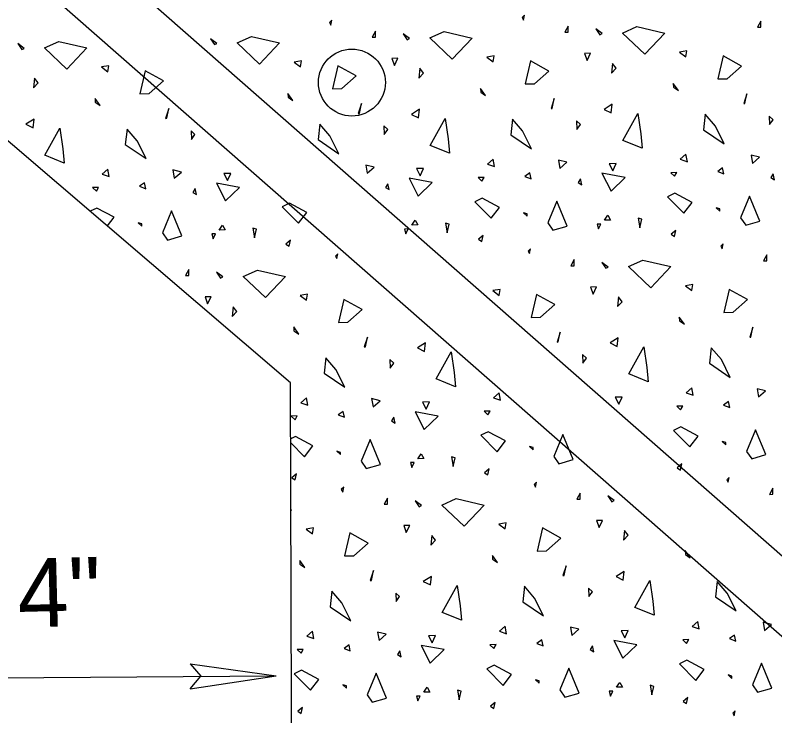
# Model space of a CAD drawing. Extents: x 1.75 to 8.12, y 0.37 to 10.28.
# Drawn here: x 4.27 to 4.933, y 3.682 to 4.294 of the extents above; entities that cross this region are included whole.
import ezdxf

# ---------------------------------------------------------------- set-up
doc = ezdxf.new("R2010")
doc.units = 0
for name, color, linetype in [('DETL-DIMS', 7, 'Continuous'), ('DETL-LINE', 7, 'Continuous'), ('DETL-NOTE', 7, 'Continuous'), ('DETL-PATT', 7, 'Continuous')]:
    doc.layers.add(name, color=color, linetype=linetype)

msp = doc.modelspace()

# ---------------------------------------------------------------- linework, layer by layer
at = {"layer": 'DETL-DIMS'}
for p, q in [((4.42275, 3.72744), (4.49784, 3.71703)), ((4.42275, 3.72744), (4.43219, 3.71656)), ((4.06589, 3.71396), (4.49784, 3.71702)), ((4.42291, 3.70556), (4.49784, 3.71703)), ((4.42291, 3.70556), (4.43219, 3.71656))]:
    msp.add_line(p, q, dxfattribs=at)
at = {"layer": 'DETL-LINE'}
msp.add_lwpolyline([(3.92029, 4.64557), (5.1805, 3.53994), (5.21677, 3.57813), (3.95655, 4.68376)], close=True, dxfattribs=at)
msp.add_lwpolyline([(4.51269, 3.21598), (4.5105, 3.97278), (4.06527, 4.35405), (3.74007, 4.41165)], dxfattribs=at)
msp.add_circle((4.56394, 4.23498), 0.02922, dxfattribs=at)
at = {"layer": 'DETL-PATT'}
for points in [[(4.71467, 4.2938), (4.71247, 4.29175), (4.71377, 4.28953)], [(4.54647, 4.28949), (4.54427, 4.28744), (4.54558, 4.28522)], [(4.75267, 4.28427), (4.74981, 4.27895), (4.75281, 4.27903)], [(4.8127, 4.28381), (4.83711, 4.27818), (4.81957, 4.25973), (4.80009, 4.27824)], [(4.92087, 4.28858), (4.918, 4.28326), (4.921, 4.28333)], [(4.58448, 4.27996), (4.58161, 4.27464), (4.58461, 4.27472)], [(4.61218, 4.27242), (4.61415, 4.27347), (4.6088, 4.27759)], [(4.64451, 4.2795), (4.66891, 4.27388), (4.65138, 4.25542), (4.6319, 4.27393)], [(4.78037, 4.27673), (4.78235, 4.27778), (4.77699, 4.2819)], [(4.30812, 4.27088), (4.33252, 4.26526), (4.31499, 4.2468), (4.29551, 4.26531)], [(4.44398, 4.26811), (4.44596, 4.26916), (4.4406, 4.27328)], [(4.47631, 4.27519), (4.50072, 4.26957), (4.48318, 4.25111), (4.4637, 4.26962)], [(4.27579, 4.2638), (4.27776, 4.26485), (4.27241, 4.26897)], [(4.68184, 4.2572), (4.6872, 4.25309), (4.68806, 4.25836)], [(4.76704, 4.26038), (4.7692, 4.25419), (4.77229, 4.26052)], [(4.85004, 4.26151), (4.85539, 4.2574), (4.85626, 4.26267)], [(4.89164, 4.23832), (4.90412, 4.24939), (4.88813, 4.25823), (4.8834, 4.23811)], [(4.51365, 4.25289), (4.519, 4.24878), (4.51987, 4.25405)], [(4.59884, 4.25608), (4.601, 4.24988), (4.60409, 4.25621)], [(4.72345, 4.23401), (4.73592, 4.24508), (4.71994, 4.25393), (4.7152, 4.2338)], [(4.79152, 4.25176), (4.79049, 4.24323), (4.79463, 4.24759)], [(4.34545, 4.24858), (4.35081, 4.24447), (4.35167, 4.24974)], [(4.38706, 4.22539), (4.39953, 4.23646), (4.38355, 4.24531), (4.37881, 4.22518)], [(4.55525, 4.2297), (4.56773, 4.24077), (4.55174, 4.24962), (4.54701, 4.22949)], [(4.62332, 4.24745), (4.62229, 4.23892), (4.62643, 4.24328)], [(4.28693, 4.23883), (4.2859, 4.2303), (4.29004, 4.23466)], [(4.84449, 4.23411), (4.84457, 4.23086), (4.8489, 4.22797)], [(4.5081, 4.22549), (4.50818, 4.22224), (4.51251, 4.21935)], [(4.67629, 4.2298), (4.67638, 4.22655), (4.6807, 4.22366)], [(4.90595, 4.21668), (4.90695, 4.2167), (4.90873, 4.22525)], [(4.3399, 4.22118), (4.33999, 4.21793), (4.34431, 4.21504)], [(4.73776, 4.21237), (4.73876, 4.21239), (4.74054, 4.22094)], [(4.40137, 4.20375), (4.40237, 4.20378), (4.40415, 4.21232)], [(4.56956, 4.20806), (4.57056, 4.20809), (4.57235, 4.21663)], [(4.61585, 4.20724), (4.62218, 4.20416), (4.62299, 4.21168)], [(4.78404, 4.21155), (4.79038, 4.20846), (4.79118, 4.21599)], [(4.64791, 4.18581), (4.64923, 4.17334), (4.6323, 4.18016), (4.64545, 4.20375)], [(4.8161, 4.19012), (4.81742, 4.17765), (4.80049, 4.18447), (4.81364, 4.20806)], [(4.87243, 4.20732), (4.87078, 4.19377), (4.88885, 4.18148), (4.8812, 4.19704)], [(4.92824, 4.20574), (4.92843, 4.19825), (4.93157, 4.20258)], [(4.27946, 4.19863), (4.28579, 4.19554), (4.2866, 4.20306)], [(4.53604, 4.1987), (4.53439, 4.18515), (4.55246, 4.17286), (4.54481, 4.18842)], [(4.59185, 4.19713), (4.59204, 4.18963), (4.59518, 4.19396)], [(4.70424, 4.20301), (4.70258, 4.18946), (4.72065, 4.17717), (4.713, 4.19273)], [(4.76005, 4.20144), (4.76024, 4.19394), (4.76338, 4.19827)], [(4.31152, 4.17719), (4.31284, 4.16472), (4.29591, 4.17154), (4.30906, 4.19513)], [(4.36785, 4.19439), (4.36619, 4.18084), (4.38426, 4.16855), (4.37661, 4.18411)], [(4.42366, 4.19282), (4.42385, 4.18532), (4.42699, 4.18965)], [(4.85557, 4.17237), (4.85043, 4.16799), (4.85674, 4.1659)], [(4.91236, 4.17158), (4.91355, 4.16435), (4.91966, 4.16976)], [(4.68738, 4.16806), (4.68224, 4.16368), (4.68854, 4.16159)], [(4.74417, 4.16727), (4.74535, 4.16005), (4.75146, 4.16545)], [(4.78851, 4.16415), (4.79167, 4.15798), (4.79476, 4.16431)], [(4.35099, 4.15945), (4.34585, 4.15506), (4.35215, 4.15297)], [(4.40778, 4.15865), (4.40896, 4.15143), (4.41508, 4.15684)], [(4.57597, 4.16296), (4.57716, 4.15574), (4.58327, 4.16115)], [(4.62032, 4.15984), (4.62347, 4.15367), (4.62656, 4.16)], [(4.88322, 4.15733), (4.88852, 4.15521), (4.88739, 4.16043)], [(4.45212, 4.15553), (4.45528, 4.14936), (4.45837, 4.15569)], [(4.61403, 4.15143), (4.62193, 4.13588), (4.63413, 4.14769)], [(4.67403, 4.15197), (4.67737, 4.1488), (4.67928, 4.1521)], [(4.71502, 4.15302), (4.72033, 4.1509), (4.71919, 4.15612)], [(4.76142, 4.1477), (4.76472, 4.14579), (4.76359, 4.15101)], [(4.78222, 4.15574), (4.79012, 4.14019), (4.80233, 4.152)], [(4.84223, 4.15628), (4.84556, 4.15311), (4.84748, 4.15641)], [(4.92962, 4.15201), (4.93292, 4.1501), (4.93178, 4.15532)], [(4.37863, 4.1444), (4.38394, 4.14228), (4.3828, 4.14751)], [(4.44583, 4.14712), (4.45373, 4.13157), (4.46594, 4.14338)], [(4.59323, 4.14339), (4.59653, 4.14148), (4.59539, 4.1467)], [(4.33765, 4.14335), (4.34098, 4.14018), (4.34289, 4.14348)], [(4.42503, 4.13909), (4.42833, 4.13717), (4.4272, 4.14239)], [(4.83952, 4.1352), (4.85364, 4.12081), (4.8609, 4.13025), (4.84594, 4.13836)], [(4.67132, 4.13089), (4.68545, 4.1165), (4.69271, 4.12594), (4.67774, 4.13406)], [(4.73948, 4.10613), (4.75189, 4.1097), (4.74283, 4.13147), (4.73507, 4.11252)], [(4.90768, 4.11044), (4.92009, 4.11401), (4.91103, 4.13578), (4.90326, 4.11683)], [(4.50313, 4.12658), (4.51725, 4.11219), (4.52451, 4.12163), (4.50955, 4.12975)], [(4.88505, 4.12461), (4.88203, 4.12553), (4.88511, 4.12261)], [(4.40309, 4.09751), (4.4155, 4.10108), (4.40644, 4.12285), (4.39868, 4.1039)], [(4.71686, 4.1203), (4.71384, 4.12123), (4.71691, 4.1183)], [(4.78741, 4.11911), (4.78977, 4.11492), (4.78452, 4.11478)], [(4.38047, 4.11168), (4.37745, 4.11261), (4.38052, 4.10969)], [(4.61922, 4.1148), (4.62158, 4.11061), (4.61633, 4.11048)], [(4.64554, 4.11222), (4.64701, 4.10376), (4.64882, 4.11131)], [(4.77811, 4.11137), (4.77922, 4.10715), (4.78136, 4.11145)], [(4.81374, 4.11653), (4.81521, 4.10807), (4.81701, 4.11562)], [(4.45102, 4.11049), (4.45338, 4.1063), (4.44813, 4.10617)], [(4.47735, 4.10791), (4.47882, 4.09945), (4.48062, 4.107)], [(4.60991, 4.10706), (4.61102, 4.10284), (4.61316, 4.10714)], [(4.84261, 4.10252), (4.84566, 4.1006), (4.84677, 4.10588)], [(4.44172, 4.10275), (4.44283, 4.09853), (4.44497, 4.10283)], [(4.67441, 4.09821), (4.67746, 4.09629), (4.67858, 4.10157)], [(4.50622, 4.0939), (4.50927, 4.09198), (4.51038, 4.09726)], [(4.88808, 4.09418), (4.88589, 4.09212), (4.88719, 4.08991)], [(4.5517, 4.08556), (4.5495, 4.0835), (4.5508, 4.08129)], [(4.71989, 4.08987), (4.71769, 4.08781), (4.719, 4.0856)], [(4.92609, 4.08465), (4.92323, 4.07932), (4.92623, 4.0794)], [(4.7579, 4.08034), (4.75503, 4.07502), (4.75803, 4.07509)], [(4.7856, 4.0728), (4.78757, 4.07385), (4.78222, 4.07796)], [(4.81793, 4.07988), (4.84233, 4.07425), (4.8248, 4.0558), (4.80532, 4.0743)], [(4.42151, 4.07172), (4.41864, 4.0664), (4.42164, 4.06647)], [(4.48154, 4.07126), (4.50594, 4.06563), (4.48841, 4.04718), (4.46893, 4.06569)], [(4.44921, 4.06418), (4.45118, 4.06523), (4.44583, 4.06934)], [(4.85526, 4.05758), (4.86062, 4.05346), (4.86148, 4.05874)], [(4.68707, 4.05327), (4.69242, 4.04915), (4.69329, 4.05443)], [(4.77226, 4.05645), (4.77442, 4.05025), (4.77751, 4.05659)], [(4.89687, 4.03439), (4.90934, 4.04546), (4.89336, 4.0543), (4.88862, 4.03417)], [(4.43587, 4.04783), (4.43803, 4.04164), (4.44112, 4.04797)], [(4.51887, 4.04896), (4.52423, 4.04484), (4.52509, 4.05012)], [(4.56048, 4.02577), (4.57295, 4.03684), (4.55697, 4.04568), (4.55223, 4.02556)], [(4.72867, 4.03008), (4.74114, 4.04115), (4.72516, 4.04999), (4.72043, 4.02986)], [(4.79674, 4.04783), (4.79571, 4.0393), (4.79985, 4.04365)], [(4.46035, 4.03921), (4.45932, 4.03068), (4.46346, 4.03504)], [(4.84971, 4.03018), (4.84979, 4.02693), (4.85412, 4.02404)], [(4.51332, 4.02156), (4.51341, 4.01831), (4.51773, 4.01542)], [(4.91118, 4.01274), (4.91218, 4.01277), (4.91396, 4.02132)], [(4.57479, 4.00413), (4.57579, 4.00415), (4.57757, 4.0127)], [(4.74298, 4.00844), (4.74398, 4.00846), (4.74576, 4.01701)], [(4.78927, 4.00762), (4.7956, 4.00453), (4.79641, 4.01205)], [(4.62107, 4.00331), (4.62741, 4.00022), (4.62821, 4.00775)], [(4.65313, 3.98188), (4.65445, 3.96941), (4.63752, 3.97622), (4.65067, 3.99982)], [(4.82133, 3.98618), (4.82265, 3.97371), (4.80572, 3.98053), (4.81887, 4.00413)], [(4.87766, 4.00338), (4.876, 3.98984), (4.89407, 3.97754), (4.88642, 3.9931)], [(4.54127, 3.99476), (4.53961, 3.98122), (4.55768, 3.96893), (4.55003, 3.98449)], [(4.59708, 3.99319), (4.59727, 3.9857), (4.60041, 3.99003)], [(4.76527, 3.9975), (4.76546, 3.99001), (4.7686, 3.99434)], [(4.8608, 3.96844), (4.85566, 3.96406), (4.86196, 3.96197)], [(4.91759, 3.96764), (4.91877, 3.96042), (4.92488, 3.96583)], [(4.52441, 3.95982), (4.51927, 3.95544), (4.52557, 3.95335)], [(4.5812, 3.95903), (4.58238, 3.9518), (4.58849, 3.95721)], [(4.6926, 3.96413), (4.68746, 3.95975), (4.69377, 3.95766)], [(4.79373, 3.96022), (4.79689, 3.95405), (4.79998, 3.96038)], [(4.62554, 3.95591), (4.6287, 3.94974), (4.63179, 3.95607)], [(4.84745, 3.95234), (4.85079, 3.94918), (4.8527, 3.95248)], [(4.88844, 3.95339), (4.89375, 3.95128), (4.89261, 3.9565)], [(4.55205, 3.94477), (4.55736, 3.94266), (4.55622, 3.94788)], [(4.61925, 3.9475), (4.62715, 3.93194), (4.63936, 3.94376)], [(4.67926, 3.94803), (4.68259, 3.94487), (4.68451, 3.94817)], [(4.51106, 3.94372), (4.5144, 3.94056), (4.51631, 3.94386)], [(4.59845, 3.93946), (4.60175, 3.93755), (4.60062, 3.94277)], [(4.84474, 3.93127), (4.85887, 3.91687), (4.86613, 3.92631), (4.85116, 3.93443)], [(4.9129, 3.9065), (4.92531, 3.91007), (4.91625, 3.93185), (4.90848, 3.91289)], [(4.67655, 3.92696), (4.69067, 3.91256), (4.69793, 3.922), (4.68297, 3.93012)], [(4.7447, 3.90219), (4.75712, 3.90576), (4.74806, 3.92754), (4.74029, 3.90858)], [(4.57651, 3.89789), (4.58892, 3.90145), (4.57986, 3.92323), (4.57209, 3.90427)], [(4.89028, 3.92068), (4.88725, 3.9216), (4.89033, 3.91868)], [(4.55389, 3.91206), (4.55086, 3.91298), (4.55394, 3.91006)], [(4.72208, 3.91637), (4.71906, 3.91729), (4.72214, 3.91437)], [(4.62444, 3.91087), (4.6268, 3.90668), (4.62155, 3.90654)], [(4.65077, 3.90829), (4.65224, 3.89983), (4.65404, 3.90737)], [(4.61514, 3.90313), (4.61625, 3.8989), (4.61839, 3.90321)], [(4.84783, 3.89858), (4.85088, 3.89666), (4.852, 3.90194)], [(4.51144, 3.88997), (4.51449, 3.88804), (4.51561, 3.89332)], [(4.67964, 3.89428), (4.68269, 3.89235), (4.6838, 3.89763)], [(4.72511, 3.88594), (4.72292, 3.88388), (4.72422, 3.88166)], [(4.89331, 3.89025), (4.89111, 3.88819), (4.89242, 3.88597)], [(4.55692, 3.88163), (4.55472, 3.87957), (4.55603, 3.87735)], [(4.93132, 3.88072), (4.92845, 3.87539), (4.93145, 3.87547)], [(4.76312, 3.87641), (4.76026, 3.87108), (4.76326, 3.87116)], [(4.79082, 3.86886), (4.7928, 3.86992), (4.78744, 3.87403)], [(4.59493, 3.8721), (4.59206, 3.86677), (4.59506, 3.86685)], [(4.62263, 3.86456), (4.6246, 3.86561), (4.61925, 3.86972)], [(4.65496, 3.87164), (4.67936, 3.86601), (4.66183, 3.84755), (4.64235, 3.86606)], [(4.77749, 3.85252), (4.77965, 3.84632), (4.78274, 3.85265)], [(4.5241, 3.84503), (4.52945, 3.84091), (4.53032, 3.84619)], [(4.60929, 3.84821), (4.61145, 3.84201), (4.61454, 3.84834)], [(4.69229, 3.84933), (4.69765, 3.84522), (4.69851, 3.85049)], [(4.7339, 3.82614), (4.74637, 3.83722), (4.73039, 3.84606), (4.72565, 3.82593)], [(4.5657, 3.82183), (4.57817, 3.83291), (4.56219, 3.84175), (4.55746, 3.82162)], [(4.63377, 3.83958), (4.63274, 3.83105), (4.63688, 3.83541)], [(4.80197, 3.84389), (4.80093, 3.83536), (4.80507, 3.83972)], [(4.85494, 3.82624), (4.85502, 3.82299), (4.85934, 3.8201)], [(4.68674, 3.82193), (4.68682, 3.81868), (4.69115, 3.81579)], [(4.51855, 3.81762), (4.51863, 3.81438), (4.52296, 3.81149)], [(4.74821, 3.8045), (4.74921, 3.80453), (4.75099, 3.81308)], [(4.58001, 3.80019), (4.58101, 3.80022), (4.58279, 3.80877)], [(4.79449, 3.80369), (4.80083, 3.8006), (4.80163, 3.80812)], [(4.6263, 3.79938), (4.63263, 3.79629), (4.63344, 3.80381)], [(4.82655, 3.78225), (4.82787, 3.76978), (4.81094, 3.7766), (4.82409, 3.80019)], [(4.88288, 3.79945), (4.88123, 3.7859), (4.8993, 3.77361), (4.89165, 3.78917)], [(4.65836, 3.77794), (4.65968, 3.76547), (4.64275, 3.77229), (4.6559, 3.79589)], [(4.71469, 3.79514), (4.71303, 3.78159), (4.7311, 3.7693), (4.72345, 3.78486)], [(4.7705, 3.79357), (4.77069, 3.78607), (4.77383, 3.7904)], [(4.54649, 3.79083), (4.54484, 3.77728), (4.56291, 3.76499), (4.55526, 3.78055)], [(4.6023, 3.78926), (4.60249, 3.78176), (4.60563, 3.78609)], [(4.69783, 3.7602), (4.69269, 3.75581), (4.69899, 3.75373)], [(4.86602, 3.76451), (4.86088, 3.76012), (4.86719, 3.75803)], [(4.92281, 3.76371), (4.924, 3.75649), (4.93011, 3.7619)], [(4.52963, 3.75589), (4.52449, 3.75151), (4.5308, 3.74942)], [(4.58642, 3.75509), (4.58761, 3.74787), (4.59372, 3.75328)], [(4.75462, 3.7594), (4.7558, 3.75218), (4.76191, 3.75759)], [(4.79896, 3.75629), (4.80212, 3.75012), (4.80521, 3.75645)], [(4.63076, 3.75198), (4.63392, 3.74581), (4.63701, 3.75214)], [(4.72547, 3.74515), (4.73078, 3.74304), (4.72964, 3.74826)], [(4.79267, 3.74787), (4.80057, 3.73232), (4.81278, 3.74414)], [(4.85268, 3.74841), (4.85601, 3.74524), (4.85793, 3.74854)], [(4.89367, 3.74946), (4.89897, 3.74734), (4.89784, 3.75257)], [(4.51629, 3.73979), (4.51962, 3.73663), (4.52154, 3.73993)], [(4.55728, 3.74084), (4.56258, 3.73873), (4.56145, 3.74395)], [(4.62448, 3.74356), (4.63238, 3.72801), (4.64458, 3.73983)], [(4.68448, 3.7441), (4.68782, 3.74093), (4.68973, 3.74423)], [(4.77187, 3.73984), (4.77517, 3.73792), (4.77404, 3.74314)], [(4.60368, 3.73553), (4.60698, 3.73361), (4.60584, 3.73883)], [(4.84997, 3.72733), (4.86409, 3.71294), (4.87135, 3.72238), (4.85639, 3.7305)], [(4.91812, 3.70257), (4.93054, 3.70614), (4.92148, 3.72791), (4.91371, 3.70896)], [(4.51358, 3.71872), (4.5277, 3.70432), (4.53496, 3.71376), (4.52, 3.72188)], [(4.68177, 3.72302), (4.6959, 3.70863), (4.70316, 3.71807), (4.68819, 3.72619)], [(4.74993, 3.69826), (4.76234, 3.70183), (4.75328, 3.72361), (4.74551, 3.70465)], [(4.58173, 3.69395), (4.59415, 3.69752), (4.58509, 3.7193), (4.57732, 3.70034)], [(4.72731, 3.71244), (4.72428, 3.71336), (4.72736, 3.71044)], [(4.8955, 3.71675), (4.89248, 3.71767), (4.89556, 3.71475)], [(4.55911, 3.70813), (4.55609, 3.70905), (4.55917, 3.70613)], [(4.62967, 3.70693), (4.63203, 3.70274), (4.62678, 3.70261)], [(4.79786, 3.71124), (4.80022, 3.70705), (4.79497, 3.70692)], [(4.82419, 3.70867), (4.82565, 3.7002), (4.82746, 3.70775)], [(4.65599, 3.70436), (4.65746, 3.69589), (4.65927, 3.70344)], [(4.78856, 3.7035), (4.78967, 3.69928), (4.79181, 3.70359)], [(4.62036, 3.69919), (4.62147, 3.69497), (4.62361, 3.69928)], [(4.68486, 3.69034), (4.68791, 3.68842), (4.68903, 3.6937)], [(4.85306, 3.69465), (4.85611, 3.69273), (4.85722, 3.69801)], [(4.51667, 3.68603), (4.51972, 3.68411), (4.52083, 3.68939)], [(4.89853, 3.68631), (4.89634, 3.68426), (4.89764, 3.68204)]]:
    msp.add_lwpolyline(points, close=True, dxfattribs=at)
for points in [[(4.35052, 4.10978), (4.35632, 4.11732), (4.34136, 4.12544), (4.33557, 4.12259)], [(4.51066, 3.9203), (4.52248, 3.90826), (4.52974, 3.91769), (4.51477, 3.92581), (4.51065, 3.92378)], [(4.51083, 3.86178), (4.51117, 3.8617), (4.51083, 3.86135)]]:
    msp.add_lwpolyline(points, dxfattribs=at)

# ---------------------------------------------------------------- texts
at = {"layer": 'DETL-NOTE'}
msp.add_text('4"', height=0.06, rotation=1.46756, dxfattribs=at).set_placement((4.27275, 3.75909))

doc.saveas('drawing.dxf')
